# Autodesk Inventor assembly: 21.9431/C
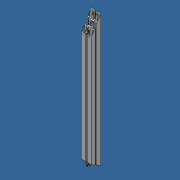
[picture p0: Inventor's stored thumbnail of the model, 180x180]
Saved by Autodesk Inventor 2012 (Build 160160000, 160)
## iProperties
Created: 2015-04
Part Number: 21.9431/C
Document SubType Name: Assembly
Designer: Admin
Description: Strengthening Element 45 x 60º
Author: Admin
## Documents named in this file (4)
- C:\Andys Backup Data\ANDY'S INVENTOR\INVENTOR LIBRARIES\PARTS LIBRARY\FEET WHEELS FLOOR FASTENING SUPPORTS\21.9431_C Strengthening Element 45 x 60º.iam
- C:\Andys Backup Data\ANDY'S INVENTOR\INVENTOR LIBRARIES\PARTS LIBRARY\FEET WHEELS FLOOR FASTENING SUPPORTS\SUBCOMPONENTS\21.9431_C Strengthening Element 45 x 60º PROFILE.ipt
- C:\Andys Backup Data\ANDY'S INVENTOR\INVENTOR LIBRARIES\PARTS LIBRARY\FASTENING ELEMENTS\SCREWS CAP\21.1208 M8X35.ipt
- C:\Andys Backup Data\ANDY'S INVENTOR\INVENTOR LIBRARIES\PARTS LIBRARY\FASTENING ELEMENTS\NUTS\21.1351_2 M8 SQUARE NUT POS FXG.ipt
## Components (5 placed, 3 different names)
1. 21.9431_C Strengthening Element 45 x 60º PROFILE:1 — Insert:1, Insert:2, Mate:2, Angle:1, Mate:4, Angle:2
2. 21.1208  M8 x 35:1 — Insert:1, Mate:1
3. 21.1208  M8 x 35:2 — Insert:2, Mate:3
4. 21.1351_2 M8 SQUARE NUT POS FXG:1 — Mate:1, Mate:2, Angle:1
5. 21.1351_2 M8 SQUARE NUT POS FXG:2 — Mate:3, Mate:4, Angle:2
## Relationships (8: Mate 4, Insert 2, Angle 2)
- Insert:1: 21.9431_C Strengthening Element 45 x 60º PROFILE:1 ↔ 21.1208  M8 x 35:1
- Insert:2: 21.9431_C Strengthening Element 45 x 60º PROFILE:1 ↔ 21.1208  M8 x 35:2
- Mate:1: 21.1208  M8 x 35:1 ↔ 21.1351_2 M8 SQUARE NUT POS FXG:1
- Mate:2: 21.9431_C Strengthening Element 45 x 60º PROFILE:1 ↔ 21.1351_2 M8 SQUARE NUT POS FXG:1
- Angle:1: 21.9431_C Strengthening Element 45 x 60º PROFILE:1 ↔ 21.1351_2 M8 SQUARE NUT POS FXG:1
- Mate:3: 21.1208  M8 x 35:2 ↔ 21.1351_2 M8 SQUARE NUT POS FXG:2
- Mate:4: 21.9431_C Strengthening Element 45 x 60º PROFILE:1 ↔ 21.1351_2 M8 SQUARE NUT POS FXG:2
- Angle:2: 21.9431_C Strengthening Element 45 x 60º PROFILE:1 ↔ 21.1351_2 M8 SQUARE NUT POS FXG:2
